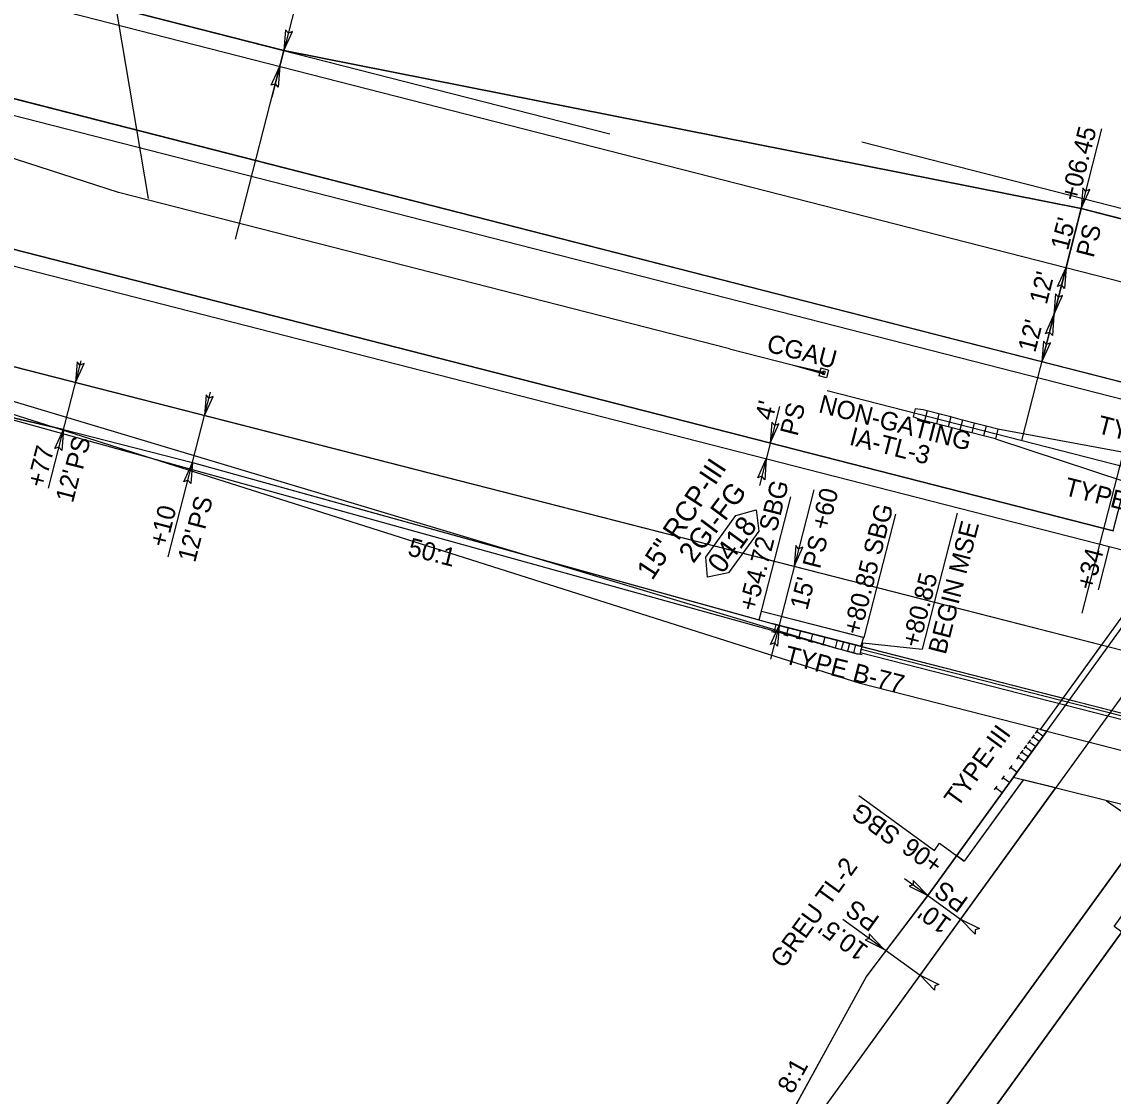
# Model space of a CAD drawing. Extents: x 1183930 to 1185370, y 573068 to 574871.
# Drawn here: x 1184226.2 to 1184495.2, y 573929 to 574193.8 of the extents above; entities that cross this region are included whole.
import ezdxf

# ---------------------------------------------------------------- set-up
doc = ezdxf.new("R2010")
doc.units = 0
for name, color, linetype in [('Default', 7, 'Continuous'), ('E_NCDOT_Terrain_Model_Flow_Arrows', 7, 'Continuous'), ('E_NCDOT_Terrain_Model_Spot_Elevation', 7, 'Continuous'), ('E_NCDOT_Terrain_Model_Triangles', 7, 'Continuous'), ('E_NCDOT_Vertical_Profile_Ground_Line', 7, 'Continuous'), ('P_NCDOT_Horizontal_Alignment', 7, 'Continuous'), ('P_NCDOT_Horizontal_Alignment_Curve_and_Spiral_Data', 7, 'Continuous'), ('P_NCDOT_Horizontal_Alignment_Direction_Label', 7, 'Continuous'), ('P_NCDOT_Horizontal_Alignment_Station_Label', 7, 'Continuous'), ('P_NCDOT_Horizontal_Alignment_Tick_Large', 7, 'Continuous'), ('P_NCDOT_Horizontal_Alignment_Tick_Small', 7, 'Continuous'), ('P_NCDOT_Vertical_Profile_Ditch_Grade_Left', 7, 'Continuous'), ('P_NCDOT_Vertical_Profile_Grade', 7, 'Continuous'), ('P_RDY_Profile_Special_Ditch_L', 7, 'Continuous'), ('P_RDY_Profile_Special_Ditch_R', 7, 'Continuous'), ('P_SMU_D_SupportLines_Text', 7, 'Continuous'), ('P_SMU_D_Unit_Label', 7, 'Continuous'), ('P_SMU_Deck', 7, 'Continuous'), ('P_SMU_SupportLines', 7, 'Continuous'), ('PC_OBJECT', 7, 'Continuous'), ('PC_PADFOOTING', 7, 'Continuous'), ('PS_HATCH', 7, 'Continuous')]:
    doc.layers.add(name, color=color, linetype=linetype)

msp = doc.modelspace()

# ---------------------------------------------------------------- linework, layer by layer
for points in [[(1184291.21, 574191.83), (1184290.79, 574186.71), (1184292.93, 574191.42), (1184291.9, 574191.02)], [(1184287.7, 574178.15), (1184289.8, 574182.84), (1184289.41, 574177.68), (1184288.7, 574178.53)], [(1184487.69, 574152.89), (1184487.27, 574147.77), (1184489.41, 574152.48), (1184488.38, 574152.07)], [(1184481.45, 574128.55), (1184483.55, 574133.24), (1184483.16, 574128.08), (1184482.45, 574128.93)], [(1184481.45, 574128.55), (1184483.55, 574133.24), (1184483.16, 574128.08), (1184482.45, 574128.93)], [(1184480.99, 574126.73), (1184480.58, 574121.61), (1184482.71, 574126.32), (1184481.68, 574125.92)], [(1184478.48, 574116.92), (1184480.58, 574121.61), (1184480.19, 574116.46), (1184479.48, 574117.31)], [(1184478.01, 574115.11), (1184477.6, 574109.99), (1184479.74, 574114.7), (1184478.7, 574114.29)], [(1184239.86, 574110.01), (1184239.45, 574104.89), (1184241.58, 574109.6), (1184240.55, 574109.2)], [(1184271.65, 574101.87), (1184271.24, 574096.75), (1184273.37, 574101.46), (1184272.34, 574101.06)], [(1184411.07, 574095.08), (1184410.66, 574089.96), (1184412.8, 574094.67), (1184411.76, 574094.27)], [(1184234.37, 574088.58), (1184236.47, 574093.27), (1184236.08, 574088.11), (1184235.37, 574088.96)], [(1184407.57, 574081.4), (1184409.67, 574086.09), (1184409.28, 574080.93), (1184408.57, 574081.78)], [(1184266.16, 574080.44), (1184268.26, 574085.13), (1184267.87, 574079.97), (1184267.16, 574080.82)], [(1184416.96, 574064.67), (1184416.55, 574059.55), (1184418.69, 574064.26), (1184417.65, 574063.86)], [(1184410.73, 574040.33), (1184412.83, 574045.02), (1184412.44, 574039.87), (1184411.73, 574040.72)], [(1184444.86, 573980.7), (1184449.47, 573978.44), (1184445.87, 573982.15), (1184445.87, 573981.05)], [(1184461.16, 573968.9), (1184457.57, 573972.58), (1184462.22, 573970.32), (1184461.17, 573969.97)], [(1184434.06, 573967.49), (1184438.67, 573965.23), (1184435.07, 573968.94), (1184435.07, 573967.83)], [(1184451.17, 573955.1), (1184447.58, 573958.78), (1184452.23, 573956.52), (1184451.18, 573956.17)]]:
    msp.add_lwpolyline(points, close=True)
at = {"layer": 'Default'}
msp.add_line((1184433.21, 574164.19), (1184675.4, 574102.19), dxfattribs=at)
at = {"layer": 'E_NCDOT_Terrain_Model_Flow_Arrows'}
msp.add_line((1184432.84, 574038.35), (1184571.16, 574002.94), dxfattribs=at)
at = {"layer": 'E_NCDOT_Terrain_Model_Spot_Elevation'}
msp.add_line((1184571.34, 574003.67), (1184433.02, 574039.08), dxfattribs=at)
at = {"layer": 'E_NCDOT_Terrain_Model_Triangles'}
for p, q in [((1184408.48, 574048.54), (1184433.79, 574042.06)), ((1184472.96, 574006.92), (1184458.47, 573986.9)), ((1184472.86, 574006.77), (1184458.47, 573986.9))]:
    msp.add_line(p, q, dxfattribs=at)
at = {"layer": 'E_NCDOT_Vertical_Profile_Ground_Line'}
for p, q in [((1184449.47, 573978.44), (1184665.23, 574276.54)), ((1184449.47, 573978.44), (1184665.23, 574276.54)), ((1184144.08, 574224.27), (1184371.09, 574166.16)), ((1184144.08, 574224.27), (1184290.79, 574186.71)), ((1184136.14, 574193.27), (1184503.1, 574099.33)), ((1184136.14, 574193.27), (1184503.1, 574099.33)), ((1184136.14, 574193.27), (1184503.1, 574099.33)), ((1184290.79, 574186.71), (1184487.27, 574147.77)), ((1184413.69, 573853.97), (1184639.53, 574165.99)), ((1184413.69, 573853.97), (1184639.53, 574165.99)), ((1184128.2, 574162.27), (1184495.16, 574068.33)), ((1184128.2, 574162.27), (1184495.16, 574068.33)), ((1184128.2, 574162.27), (1184495.16, 574068.33)), ((1184487.27, 574147.77), (1184526.03, 574137.85)), ((1184187.79, 574104.7), (1184236.47, 574093.27)), ((1184236.47, 574093.27), (1184268.26, 574085.13)), ((1184268.26, 574085.13), (1184412.83, 574045.02)), ((1184495.16, 574068.33), (1184498.26, 574080.44)), ((1184495.16, 574068.33), (1184498.26, 574080.44)), ((1184412.83, 574045.02), (1184569.95, 574004.8)), ((1184412.83, 574045.02), (1184594.42, 573998.53)), ((1184434.28, 573958.31), (1184449.47, 573978.44)), ((1184434.28, 573958.31), (1184449.47, 573978.44)), ((1184409.04, 573912.35), (1184434.28, 573958.31)), ((1184409.04, 573912.35), (1184434.28, 573958.31))]:
    msp.add_line(p, q, dxfattribs=at)
at = {"layer": 'P_NCDOT_Horizontal_Alignment'}
for p, q in [((1184397.22, 573889.19), (1184673.34, 574270.68)), ((1184405.59, 573859.83), (1184695.92, 574260.95)), ((1184143.08, 574220.4), (1184971.37, 574008.35)), ((1184143.08, 574220.4), (1184977.73, 574006.73)), ((1184137.13, 574197.15), (1184965.42, 573985.1)), ((1184137.13, 574197.15), (1184971.78, 573983.48)), ((1184127.21, 574158.4), (1184955.5, 573946.35)), ((1184127.21, 574158.4), (1184961.86, 573944.73)), ((1184034.09, 574157.29), (1184427, 574039.4)), ((1184432.78, 574030.72), (1184034.09, 574157.29)), ((1184031.97, 574149), (1184432.31, 574037.93)), ((1184121.26, 574135.15), (1184949.55, 573923.1)), ((1184121.26, 574135.15), (1184955.9, 573921.48)), ((1184478.79, 574018.94), (1184432.78, 574030.72))]:
    msp.add_line(p, q, dxfattribs=at)
at = {"layer": 'P_NCDOT_Horizontal_Alignment_Curve_and_Spiral_Data'}
msp.add_line((1184433.21, 574039.8), (1184571.53, 574004.39), dxfattribs=at)
at = {"layer": 'P_NCDOT_Horizontal_Alignment_Direction_Label'}
for p, q in [((1184477.22, 574019.34), (1184562.83, 574137.61)), ((1184478.79, 574018.94), (1184564.39, 574137.21)), ((1184477.22, 574019.34), (1184478.79, 574018.94))]:
    msp.add_line(p, q, dxfattribs=at)
at = {"layer": 'P_NCDOT_Horizontal_Alignment_Station_Label'}
for p, q in [((1184470.42, 574007.38), (1184478.79, 574018.94)), ((1184478.79, 574018.94), (1184524.61, 574007.21))]:
    msp.add_line(p, q, dxfattribs=at)
msp.add_lwpolyline([(1184516.55, 573996.08), (1184470.52, 574007.53), (1184478.79, 574018.94), (1184524.61, 574007.21)], close=True, dxfattribs=at)
at = {"layer": 'P_NCDOT_Horizontal_Alignment_Tick_Large'}
for p, q in [((1184236.47, 574093.27), (1184268.26, 574085.13)), ((1184500, 574087.22), (1184466.75, 574093.41)), ((1184466.13, 574090.99), (1184498.26, 574080.44)), ((1184268.26, 574085.13), (1184412.83, 574045.02)), ((1184467.79, 574003.75), (1184449.47, 573978.44)), ((1184514.4, 573993.1), (1184413.69, 573853.97))]:
    msp.add_line(p, q, dxfattribs=at)
at = {"layer": 'P_NCDOT_Horizontal_Alignment_Tick_Small'}
for p, q in [((1184236.47, 574093.27), (1184199.75, 574101.89)), ((1184449.47, 573978.44), (1184434.39, 573958.5))]:
    msp.add_line(p, q, dxfattribs=at)
at = {"layer": 'P_NCDOT_Vertical_Profile_Ditch_Grade_Left'}
msp.add_lwpolyline([(1184400.58, 574113.19), (1184250.03, 574151.73), (1184182.69, 574173.53)], dxfattribs=at)
at = {"layer": 'P_NCDOT_Vertical_Profile_Grade'}
for p, q in [((1184433.21, 574039.8), (1184411.05, 574045.48)), ((1184412.08, 574043.15), (1184410.97, 574043.43)), ((1184412.02, 574045.23), (1184411.52, 574043.29)), ((1184415.05, 574044.45), (1184414.55, 574042.52)), ((1184418.07, 574043.68), (1184417.58, 574041.74)), ((1184421.1, 574042.9), (1184420.6, 574040.97)), ((1184415.1, 574042.37), (1184413.99, 574042.66)), ((1184418.13, 574041.6), (1184417.02, 574041.88)), ((1184421.16, 574040.82), (1184420.05, 574041.11)), ((1184424.19, 574040.05), (1184423.08, 574040.33)), ((1184424.13, 574042.13), (1184423.63, 574040.19)), ((1184427.16, 574041.35), (1184426.66, 574039.42)), ((1184428.67, 574040.97), (1184428.17, 574039.03)), ((1184430.18, 574040.58), (1184429.69, 574038.64)), ((1184431.7, 574040.19), (1184431.2, 574038.25)), ((1184427.21, 574039.27), (1184426.1, 574039.56)), ((1184428.73, 574038.89), (1184427.62, 574039.17)), ((1184430.24, 574038.5), (1184429.13, 574038.78)), ((1184431.76, 574038.11), (1184430.65, 574038.4)), ((1184433.27, 574037.72), (1184432.16, 574038.01)), ((1184433.21, 574039.8), (1184432.71, 574037.87)), ((1184478.79, 574018.94), (1184467.79, 574003.75)), ((1184476.59, 574019.31), (1184475.91, 574018.39)), ((1184477.87, 574017.68), (1184476.25, 574018.85)), ((1184474.75, 574016.78), (1184474.08, 574015.85)), ((1184476.04, 574015.15), (1184474.42, 574016.32)), ((1184475.67, 574018.05), (1184475, 574017.12)), ((1184476.95, 574016.41), (1184475.33, 574017.58)), ((1184472.92, 574014.25), (1184472.25, 574013.32)), ((1184474.21, 574012.61), (1184472.58, 574013.79)), ((1184473.84, 574015.52), (1184473.17, 574014.59)), ((1184475.12, 574013.88), (1184473.5, 574015.05)), ((1184470.17, 574010.45), (1184469.5, 574009.53)), ((1184472, 574012.99), (1184471.33, 574012.06)), ((1184473.29, 574011.35), (1184471.67, 574012.52)), ((1184468.34, 574007.92), (1184467.67, 574006.99)), ((1184471.46, 574008.82), (1184469.84, 574009.99)), ((1184466.51, 574005.39), (1184465.84, 574004.46)), ((1184469.62, 574006.29), (1184468, 574007.46)), ((1184467.79, 574003.75), (1184466.17, 574004.93))]:
    msp.add_line(p, q, dxfattribs=at)
at = {"layer": 'P_RDY_Profile_Special_Ditch_L'}
for p, q in [((1184446.09, 574097.41), (1184445.84, 574096.44)), ((1184446.34, 574098.38), (1184446.09, 574097.41)), ((1184448.34, 574098.12), (1184446.34, 574098.38)), ((1184449.31, 574097.88), (1184448.34, 574098.12)), ((1184449.31, 574097.88), (1184448.69, 574095.45)), ((1184452.21, 574097.13), (1184449.31, 574097.88)), ((1184452.21, 574097.13), (1184451.59, 574094.71)), ((1184455.12, 574096.39), (1184452.21, 574097.13)), ((1184447.72, 574095.7), (1184445.84, 574096.44)), ((1184448.69, 574095.45), (1184447.72, 574095.7)), ((1184451.59, 574094.71), (1184448.69, 574095.45)), ((1184454.5, 574093.97), (1184451.59, 574094.71)), ((1184455.12, 574096.39), (1184454.5, 574093.97)), ((1184457.41, 574093.22), (1184454.5, 574093.97)), ((1184458.03, 574095.64), (1184455.12, 574096.39)), ((1184458.03, 574095.64), (1184457.41, 574093.22)), ((1184460.93, 574094.9), (1184458.03, 574095.64)), ((1184460.93, 574094.9), (1184460.31, 574092.48)), ((1184463.84, 574094.16), (1184460.93, 574094.9)), ((1184463.84, 574094.16), (1184463.22, 574091.73)), ((1184466.75, 574093.41), (1184463.84, 574094.16)), ((1184460.31, 574092.48), (1184457.41, 574093.22)), ((1184463.22, 574091.73), (1184460.31, 574092.48)), ((1184466.13, 574090.99), (1184463.22, 574091.73)), ((1184466.75, 574093.41), (1184466.13, 574090.99))]:
    msp.add_line(p, q, dxfattribs=at)
at = {"layer": 'P_RDY_Profile_Special_Ditch_R'}
for p, q in [((1184400.58, 574113.19), (1184416.08, 574109.22)), ((1184416.08, 574109.22), (1184423.83, 574107.24)), ((1184416.08, 574109.22), (1184423.88, 574107.42)), ((1184416.08, 574109.22), (1184423.76, 574107.04)), ((1184416.08, 574109.22), (1184416.08, 574109.22)), ((1184423.11, 574108.45), (1184422.62, 574106.52)), ((1184425.05, 574107.96), (1184423.11, 574108.45)), ((1184423.7, 574107.7), (1184423.49, 574106.89)), ((1184424.18, 574107.58), (1184423.7, 574107.7)), ((1184424.18, 574107.58), (1184423.97, 574106.77)), ((1184425.05, 574107.96), (1184424.55, 574106.02)), ((1184424.55, 574106.02), (1184422.62, 574106.52)), ((1184423.97, 574106.77), (1184423.49, 574106.89))]:
    msp.add_line(p, q, dxfattribs=at)
at = {"layer": 'P_SMU_D_SupportLines_Text'}
msp.add_lwpolyline([(1184394.8, 574061.87), (1184402.2, 574072.07), (1184407.22, 574073.49), (1184407.8, 574068.2), (1184400.4, 574058), (1184395.16, 574056.86), (1184394.8, 574061.87)], dxfattribs=at)
at = {"layer": 'P_SMU_D_Unit_Label'}
for p, q in [((1184424.65, 574102.9), (1184608.83, 574055.75)), ((1184493.54, 574001.8), (1184493.54, 574001.8))]:
    msp.add_line(p, q, dxfattribs=at)
at = {"layer": 'P_SMU_Deck'}
for p, q in [((1184278.89, 574140.21), (1184290.79, 574186.71)), ((1184472.64, 574090.61), (1184487.27, 574147.77)), ((1184487.54, 574047.99), (1184511.87, 574143.02))]:
    msp.add_line(p, q, dxfattribs=at)
at = {"layer": 'PC_OBJECT'}
for p, q in [((1184290.79, 574186.71), (1184144.08, 574224.27)), ((1184143.08, 574220.4), (1184547.76, 574116.8)), ((1184136.14, 574193.27), (1184503.1, 574099.33)), ((1184495.16, 574068.33), (1184128.2, 574162.27)), ((1184127.21, 574158.4), (1184507.42, 574061.06)), ((1184478.79, 574018.94), (1184449.47, 573978.44)), ((1184397.22, 573889.19), (1184480.88, 574004.78)), ((1184505.98, 573998.53), (1184405.59, 573859.83)), ((1184434.39, 573958.5), (1184409.04, 573912.35))]:
    msp.add_line(p, q, dxfattribs=at)
for points in [[(1184532.63, 574095.9), (1184476.98, 574110.15), (1184137.13, 574197.15)], [(1184515.9, 574140.44), (1184487.27, 574147.77), (1184290.79, 574186.71)], [(1184472.86, 574006.77), (1184458.47, 573986.9), (1184456.58, 573988.27)], [(1184480.88, 574004.78), (1184480.99, 574004.94), (1184472.96, 574006.92), (1184472.86, 574006.77)], [(1184413.69, 573853.97), (1184497.26, 573969.42), (1184495.37, 573970.79), (1184514.01, 573996.54)], [(1184456.58, 573988.27), (1184450.25, 573979.52), (1184434.39, 573958.5)]]:
    msp.add_lwpolyline(points, dxfattribs=at)
msp.add_lwpolyline([(1184432.95, 574039.87), (1184482.84, 574027.1), (1184492.29, 574040.16), (1184121.26, 574135.15), (1184120.27, 574131.27), (1184187.79, 574104.7), (1184236.47, 574093.27), (1184268.26, 574085.13), (1184407.93, 574046.38), (1184408.48, 574048.54), (1184433.66, 574042.1)], close=True, dxfattribs=at)
at = {"layer": 'PC_PADFOOTING'}
for p, q in [((1184246.79, 574212.53), (1184257.39, 574150.22)), ((1184297.85, 574214.26), (1184287.86, 574175.24)), ((1184492.3, 574167.42), (1184483.55, 574133.24)), ((1184483.55, 574133.24), (1184477.6, 574109.99)), ((1184232.78, 574078.83), (1184240.81, 574110.2)), ((1184262.31, 574061.88), (1184272.71, 574102.49)), ((1184412.97, 574098.97), (1184407.97, 574079.46)), ((1184421.38, 574078.42), (1184410.7, 574036.7)), ((1184407.9, 574046.28), (1184415.69, 574076.69)), ((1184433.79, 574042.06), (1184441.57, 574072.47)), ((1184456.69, 574072.68), (1184448.11, 574039.16)), ((1184494.17, 574064.46), (1184491.44, 574053.79)), ((1184433.44, 574040.7), (1184432.84, 574038.35)), ((1184433.44, 574040.7), (1184448.11, 574039.16)), ((1184432.45, 574003.04), (1184451.1, 573989.54)), ((1184451.1, 573989.54), (1184452.38, 573991.31)), ((1184452.38, 573991.31), (1184458.47, 573986.9)), ((1184443.75, 573982.58), (1184457.57, 573972.58)), ((1184428.53, 573972.57), (1184447.58, 573958.78))]:
    msp.add_line(p, q, dxfattribs=at)
at = {"layer": 'PS_HATCH'}
msp.add_line((1184493.54, 574001.8), (1184585.45, 573937.33), dxfattribs=at)

# ---------------------------------------------------------------- texts
at = {"layer": 'E_NCDOT_Vertical_Profile_Ground_Line'}
msp.add_text('15" RCP-III ', height=5, rotation=56.5598, dxfattribs=at).set_placement((1184381.57, 574055.92))
at = {"layer": 'P_SMU_D_SupportLines_Text'}
msp.add_text('0418', height=5, rotation=54.0376, dxfattribs=at).set_placement((1184398.89, 574057.48))
at = {"layer": 'P_SMU_SupportLines'}
msp.add_text('2GI-FG', height=5, rotation=53.1043, dxfattribs=at).set_placement((1184391.7, 574060.09))
at = {"layer": 'PC_PADFOOTING'}
for s, rotation, p in [('+06.45', 75.6405, (1184486.51, 574149.34)), ("15'", 75.6405, (1184484.01, 574137.23)), ('PS', 75.6405, (1184490.31, 574135.45)), ("12'", 75.6405, (1184478.77, 574123.92)), ("12'", 75.6405, (1184475.94, 574112.07)), ("4'", 75.6405, (1184411.16, 574095.3)), ('PS', 75.6405, (1184417.35, 574091.45)), ('PS', 75.6405, (1184241.23, 574083.14)), ('+77', 75.6405, (1184231.72, 574078.73)), ("12'", 75.6405, (1184238.79, 574075.03)), ('+54.72 SBG', 75.6405, (1184407.12, 574048.24)), ('+60', 75.6405, (1184424.97, 574068.26)), ('PS', 75.6405, (1184271.34, 574068.43)), ('+10', 75.6405, (1184261.83, 574064.02)), ('+80.85 SBG', 75.6405, (1184432.86, 574042.42)), ('BEGIN MSE', 75.6405, (1184453.87, 574037.63)), ("12'", 75.6405, (1184268.9, 574060.32)), ('PS', 75.6405, (1184422.89, 574058.75)), ('+34', 75.6405, (1184490.29, 574053.46)), ("15'", 75.6405, (1184419.78, 574048.57)), ('+80.85', 75.6405, (1184447.33, 574039.31)), ('SBG', 144.103, (1184443.08, 573994.13)), ('+06', 144.103, (1184453.62, 573987)), ('PS', 144.103, (1184459.77, 573977.58)), ('PS', 144.103, (1184437.9, 573972.93)), ("10'", 144.103, (1184455.64, 573972.23)), ("10.5'", 144.103, (1184435.15, 573965.62)), ('8:1', 61.1127, (1184416.11, 573929.27))]:
    msp.add_text(s, height=4.5, rotation=rotation, dxfattribs=at).set_placement(p)
at = {"layer": 'PS_HATCH'}
for s, rotation, p in [('CGAU', 345.6405, (1184409.51, 574112.56)), ('NON-GATING', 345.6405, (1184422.33, 574097.59)), ('TYPE B-77', 345.6405, (1184490.98, 574092.48)), ('IA-TL-3', 345.6405, (1184429.91, 574089.61)), ('TYPE B-77', 345.6405, (1184482.85, 574077.2)), ('50:1', 345.6405, (1184321.08, 574062.33)), ('TYPE B-77', 345.6405, (1184413.86, 574035.71)), ('TYPE-III', 54.0376, (1184456.82, 573999.93)), ('GREU TL-2 ', 54.0376, (1184413.96, 573960.2))]:
    msp.add_text(s, height=4.5, rotation=rotation, dxfattribs=at).set_placement(p)

doc.saveas('drawing.dxf')
